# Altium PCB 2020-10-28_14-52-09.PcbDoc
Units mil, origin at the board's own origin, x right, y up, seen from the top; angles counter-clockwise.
Board outline 2200 x 1600 mil, 4 copper layers (Top Layer, MidLayer1, MidLayer2, Bottom Layer); 14 components, 6 nets, 34 pads, 44 vias.
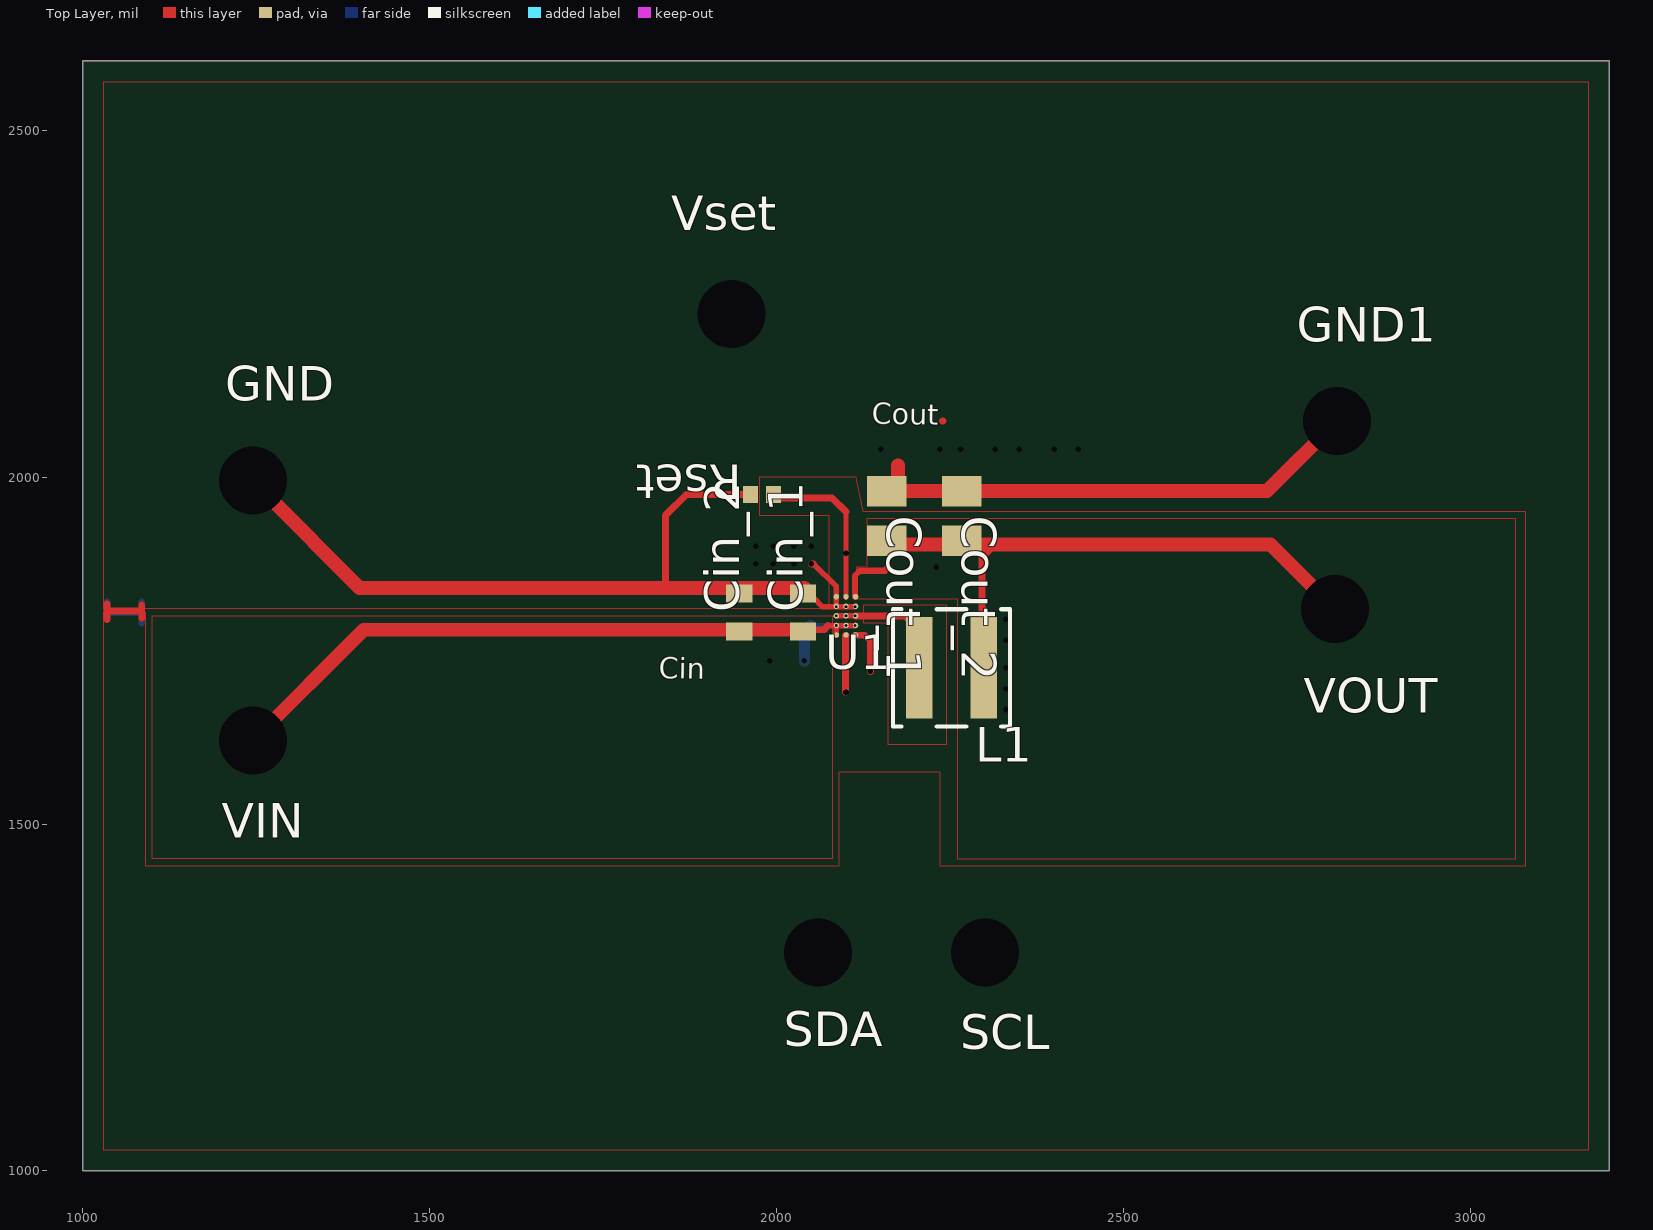
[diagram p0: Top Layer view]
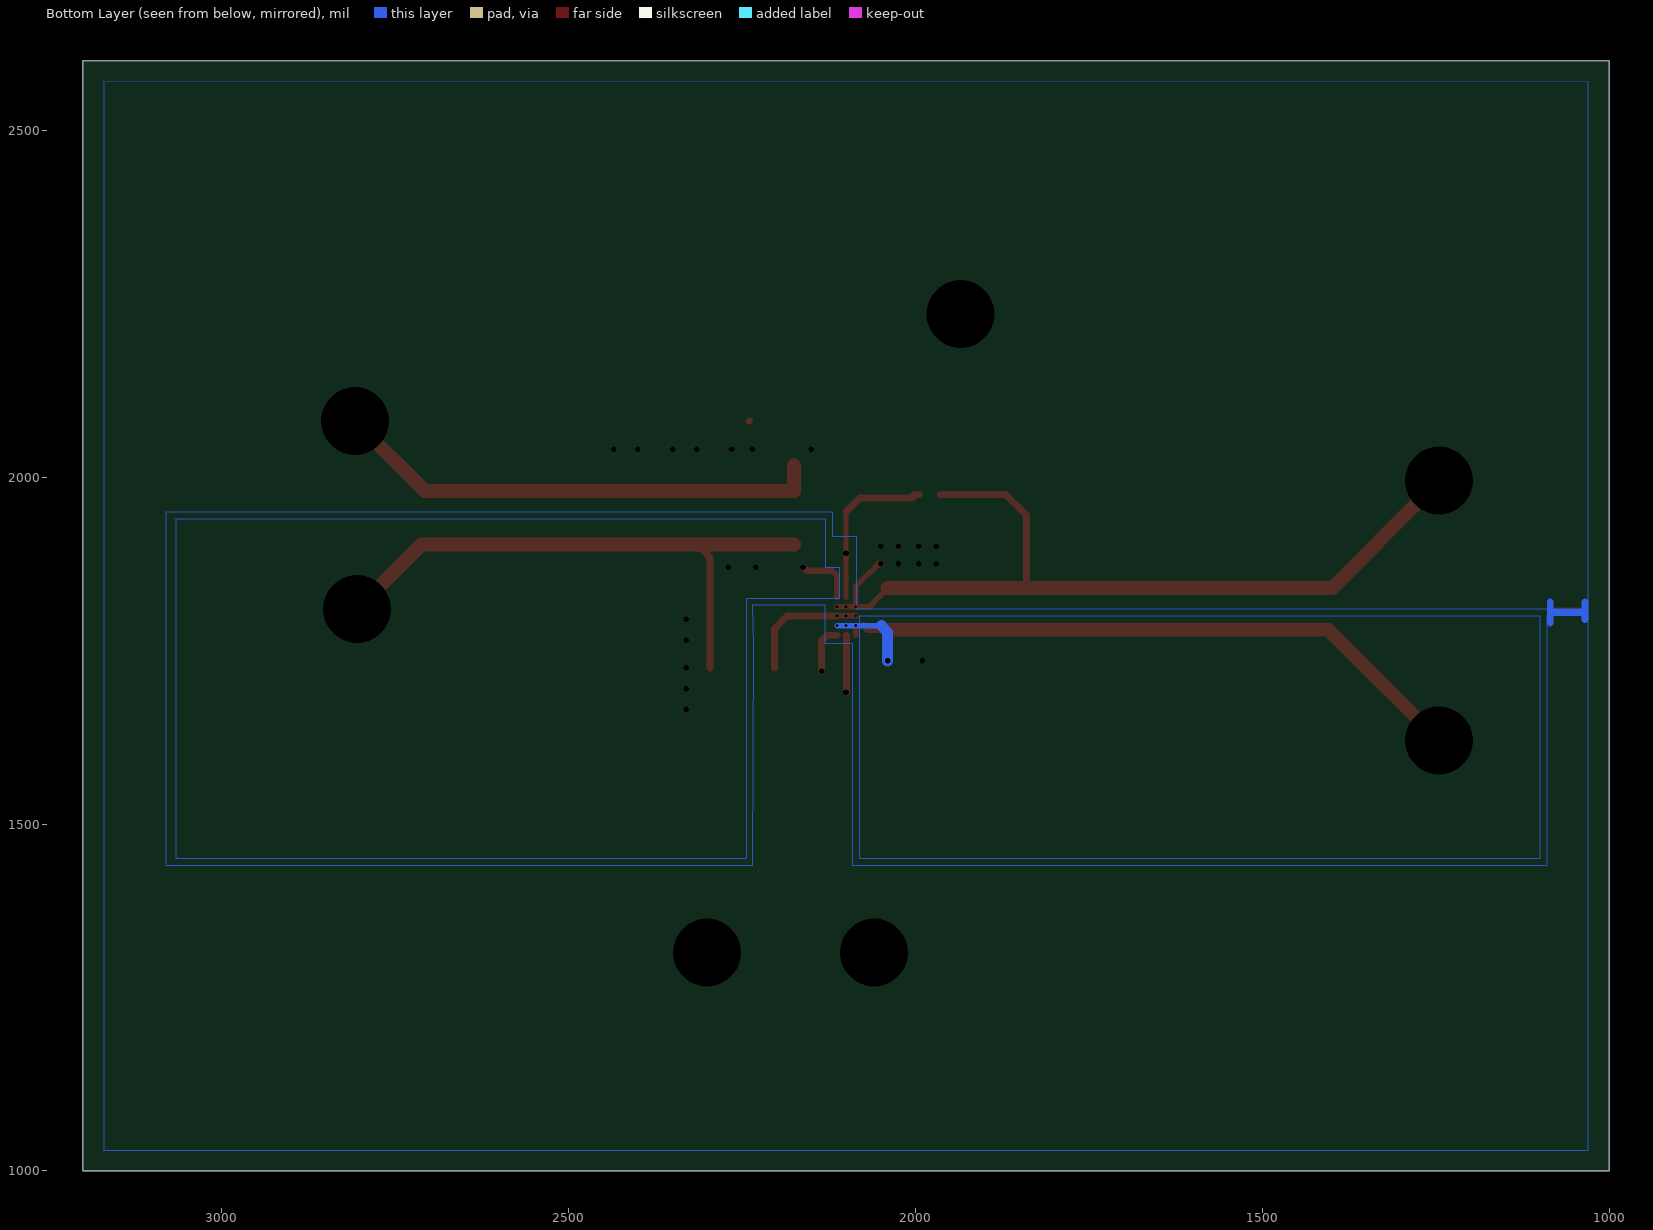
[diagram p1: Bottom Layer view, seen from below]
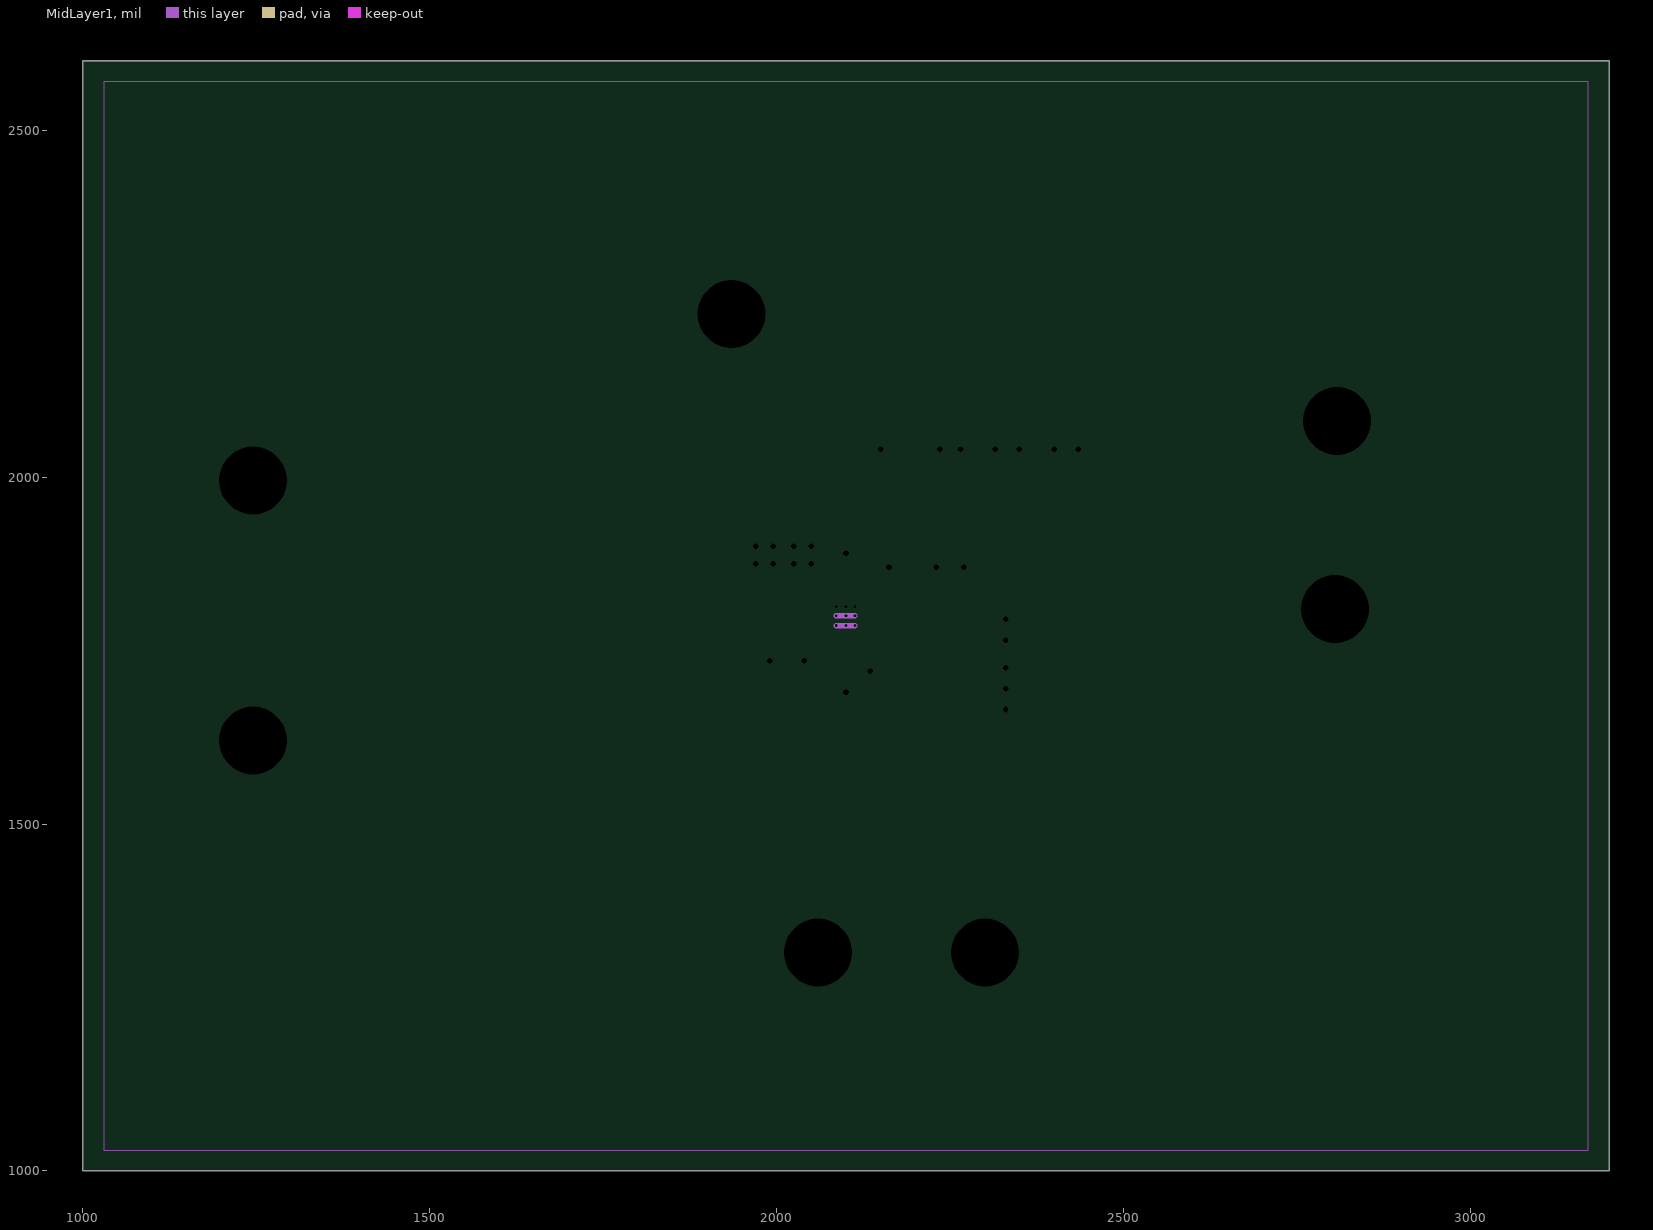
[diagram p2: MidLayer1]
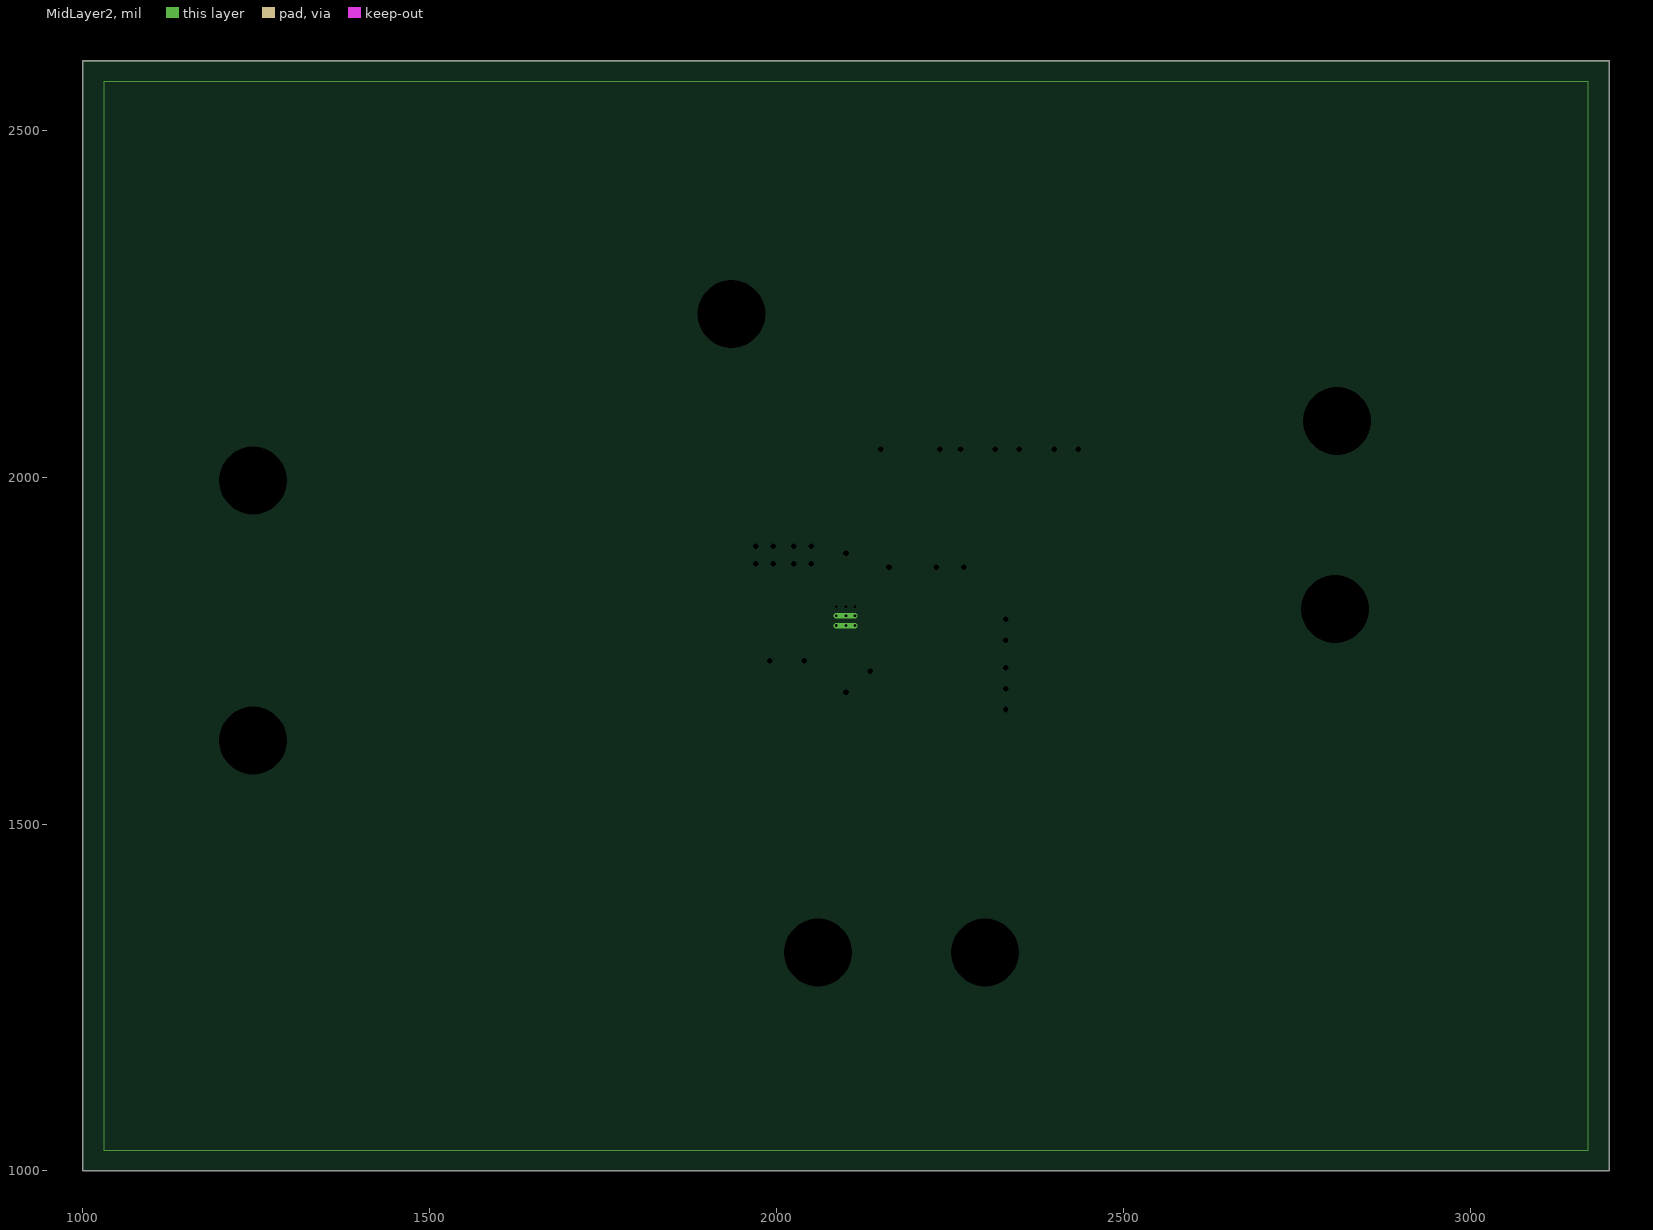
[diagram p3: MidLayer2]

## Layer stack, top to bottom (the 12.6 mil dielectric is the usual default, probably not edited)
Top Layer: signal copper 1.4
Dielectric: core 12.6, FR-4, Dk 4.8
MidLayer1: signal copper 1.4
Dielectric: prepreg 12.6, FR-4, Dk 4.8
MidLayer2: signal copper 1.4
Dielectric: core 12.6, FR-4, Dk 4.8
Bottom Layer: signal copper 1.4

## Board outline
1000,1000 3200,1000 3200,2600 1000,2600

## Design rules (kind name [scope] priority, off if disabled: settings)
PlaneConnect [All] p0: scope1count=1 scope1_0_kind=Board scope1_0_value=Board scope2count=1 scope2_0_kind=Board scope2_0_value=Board commentlength=0 planeconnectstyle=Direct reliefexpansion=20 reliefentries=4 reliefconductorwidth=10 reliefairgap=10
PlaneConnect [All] p1: planeconnectstyle=Direct reliefexpansion=20 reliefentries=4 reliefconductorwidth=10 reliefairgap=10
PolygonConnect [All] p0: scope1count=1 scope1_0_kind=Board scope1_0_value=Board scope2count=1 scope2_0_kind=Board scope2_0_value=Board commentlength=0 connectstyle=Direct reliefconductorwidth=10 reliefentries=4 polygonreliefangle="90 Angle"
PolygonConnect [All] p1: connectstyle=Direct reliefconductorwidth=10 reliefentries=4 polygonreliefangle="90 Angle"

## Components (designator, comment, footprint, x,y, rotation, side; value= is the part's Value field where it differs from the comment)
Cin_1 "" 0603 2038,1805 r90 top
Cin_2 "" 0603 1946,1805 r90 top
Cout_1 "" 0805 2159,1944 r270 top
Cout_2 "" 0805 2267,1944 r270 top
GND "" TP-1502 1244,1994 r0 top
GND1 "" TP-1502 2807,2081 r0 top
L1 "" XAL4020 2252,1725 r0 top
Rset "" 0402 1979,1975 r180 top
SCL "" TP-1502 2300,1314 r0 top
SDA "" TP-1502 2059,1314 r0 top
U1 "" YCG0015ACAC 2100,1800 r0 top
VIN "" TP-1502 1244,1620 r0 top
VOUT "" TP-1502 2805,1809 r0 top
Vset "" TP-1502 1935,2235 r0 top

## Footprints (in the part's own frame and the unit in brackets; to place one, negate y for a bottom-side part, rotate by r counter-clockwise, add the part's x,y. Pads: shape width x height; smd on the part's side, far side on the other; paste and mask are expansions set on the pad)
0402 [mil]
  rect 22x24 smd: 1(-16.5,0) 2(16.5,0)
0603 [mil]
  rect 26x38 smd: 1(-27.5,0) 2(27.5,0)
0805 [mil]
  rect 44x57 smd: 1(-35.5,0) 2(35.5,0)
TP-1502 [mil]
  round 65 / inner round 0 / far side round 65 hole 32: 1(0,0)
XAL4020 [mil]
  rect 38x146 smd: 1(-46.5,0) 2(46.5,0)
  silkscreen extent -84,-84 84,84
YCG0015ACAC [mm]
  round 0.2 smd: 1(-0.35,0.7) 2(0,0.7) 3(0.35,0.7) 4(-0.35,0.35) 5(0,0.35) 6(0.35,0.35) 7(-0.35,0) 8(0,0) 9(0.35,0) 10(-0.35,-0.35) 11(0,-0.35) 12(0.35,-0.35) 13(-0.35,-0.7) 14(0,-0.7) 15(0.35,-0.7)

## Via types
v1: diameter 0, hole 8, Top Layer to Bottom Layer, 28 vias
v2: diameter 0, hole 4, Top Layer to Bottom Layer, 9 vias
v3: diameter 0, hole 98, Top Layer to Bottom Layer, 7 vias

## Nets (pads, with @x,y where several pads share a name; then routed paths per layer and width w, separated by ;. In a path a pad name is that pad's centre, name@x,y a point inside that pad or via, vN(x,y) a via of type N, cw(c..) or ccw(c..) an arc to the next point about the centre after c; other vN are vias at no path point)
0: Cin_1.2 Cin_2.2 Cout_1.1 Cout_2.1 GND1.1 GND.1 Rset.1 Rset.2 U1.1 U1.2 U1.4 U1.5 U1.6 Vset.1 | length 2912
  Top Layer w7.8: Cin_1.2@2040,1840 2066,1813 v2(2086,1813) v2(2100,1813) v2(2113,1813) ; U1.1@2086,1827 2086,1842 ; U1.2@2100,1827 v1(2100,1890) 2100,1950
  Top Layer w8: 2053,1875 2086,1842 ; v2(2086,1813) U1.1@2086,1827
  Top Layer w10: 1035,1795 1035,1807 ; 1035,1817 1035,1807 ; 1085,1797 1085,1807 ; 1085,1816 1085,1807 ; 1840,1840 1840,1945 1870,1975 Rset.2@1960,1975 ; v3(1935,2235) Vset.1@1940,2240 ; Rset.2@1955,1974.5 Rset.2@1964,1974.5 ; Rset.1@1994,1974.5 Rset.1@2003,1974.5 ; Rset.1@1999,1975 2004,1970 2080,1970 2100,1950 ; v1(2050,1875) 2053,1875 ; 2239,2081 2240,2081 ; 1035,1807 1085,1807
  Top Layer w20: v3(1245,1995) 1265,1975 1399,1840 1840,1840 Cin_1.2@2040,1840 ; 2175,2017 2175,1980 2707,1980 v3(2808,2081)
  Mid-Layer 4 w10: v3(1935,2235) 2055,2235 2100,2190 v1(2100,1890)
  Bottom Layer w10: 1035,1795 1035,1805 ; 1035,1820 1035,1805 ; 1085,1790 1085,1805 ; 1085,1820 1085,1805 ; 1035,1805 1085,1805
  other v1: 1970,1875 1995,1875 2025,1875 1970,1900 1995,1900 2025,1900 2050,1900 2150,2040 2235,2040 2265,2040 2315,2040 2350,2040 2400,2040 2435,2040
4: Cin_1.1 Cin_2.1 U1.10 U1.11 U1.12 U1.13 VIN.1 | length 1177.2
  Top Layer w7.8: 2074,1786 v2(2086,1786) ; U1.13@2086,1772 v2(2086,1786) ; v2(2113,1786) v2(2100,1786) v2(2086,1786)
  Top Layer w10: Cin_1.1@2040,1780 2068,1780 2074,1786
  Top Layer w20: v3(1245,1620) 1405,1780 Cin_1.1@2040,1780
  MidLayer1 w7.8: v2(2086,1786) v2(2100,1786) v2(2113,1786)
  MidLayer2 w7.8: v2(2086,1786) v2(2100,1786) v2(2113,1786)
  Mid-Layer 3 w7.8: v2(2086,1786) v2(2100,1786) v2(2113,1786)
  Mid-Layer 4 w7.8: v2(2086,1786) v2(2100,1786) v2(2113,1786)
  Bottom Layer w7.8: 2049,1786 v2(2086,1786) v2(2100,1786) v2(2113,1786)
  Bottom Layer w15.7: v1(2040,1735) 2040,1776 2049,1786
  other v1: 1990,1735
7: Cout_1.2 Cout_2.2 L1.2 U1.3 VOUT.1 | length 1014.5
  Top Layer w8: U1.3@2113,1827 2113,1858 2120,1865
  Top Layer w10: 2120,1865 2156,1865 v1(2162,1870) ; L1.2@2296,1725 2296,1884 2315,1903
  Top Layer w20: Cout_1.2@2175,1903 2315,1903 2712,1903 v3(2805,1810)
  Mid-Layer 4 w7.8: v1(2230,1870) v1(2270,1870) 2304,1870 2305,1869
  other v1: 2330,1665 2330,1695 2330,1725 2330,1765 2330,1795
13: SCL.1 U1.15 | length 543
  Top Layer w10: U1.15@2113,1772 2127,1772 2135,1765 v1(2135,1720)
  Mid-Layer 4 w10: v1(2135,1720) 2135,1550 2300,1385 v3(2300,1315)
14: SDA.1 U1.14 | length 474.6
  Top Layer w10: 2099,1690 2099,1772 U1.14@2100,1772
  Mid-Layer 4 w10: v3(2060,1315) 2060,1510 2100,1550 v1(2100,1690)
15: L1.1 U1.7 U1.8 U1.9 | length 289.2
  Top Layer w7.8: v2(2086,1800) v2(2100,1800) v2(2113,1800)
  Top Layer w10: v2(2113,1800) 2185,1800 2203,1781 L1.1@2203,1725
  MidLayer1 w7.8: v2(2086,1800) v2(2100,1800) v2(2113,1800)
  MidLayer2 w7.8: v2(2086,1800) v2(2100,1800) v2(2113,1800)
  Mid-Layer 3 w7.8: v2(2086,1800) v2(2100,1800) v2(2113,1800)
  Mid-Layer 4 w7.8: v2(2086,1800) v2(2100,1800) v2(2113,1800)

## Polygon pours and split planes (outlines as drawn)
4 on Top Layer " " (solid, pour order 2): 2080,1800 2080,1450 1100,1450 1100,1800
15 on Top Layer " " (solid, pour order 3): 2245,1815 2125,1815 2125,1790 2160,1790 2160,1615 2245,1615
7 on Top Layer " " (solid, pour order 4): 2130,1870 2115,1870 2115,1825 2260,1825 2260,1450 3065,1450 3065,1940 2130,1940
0 on Top Layer " " (solid, pour order 10): 1975,2000 1975,1945 2075,1945 2075,1810 1030,1810 1030,2570 3170,2570 3170,1030 1030,1030 1030,1805 1090,1805 1090,1440 2090,1440 2090,1575 2235,1575 2235,1440 3080,1440 3080,1950 2225,1950 2125,1950 2115,2000
7 on Bottom Layer " " (solid, pour order 0): 2130,1870 2110,1870 2110,1825 2244,1825 2244,1450 3065,1450 3065,1940 2680,1940 2130,1940
4 on Bottom Layer " " (solid, pour order 1): 1100,1800 1100,1450 2080,1450 2080,1800
0 on Bottom Layer " " (solid, pour order 9): 2130,1760 2130,1815 2235,1815 2234,1760 2235,1440 3080,1440 3080,1950 2120,1950 2120,1915 2085,1915 2085,1810 1030,1810 1030,2569 3170,2570 3170,1030 1030,1030 1030,1800 1090,1800 1090,1440 2090,1440 2090,1760
0 on Mid-Layer 4 " " (solid, pour order 5): 1030,2570 3170,2570 3169,1030 1029,1030
0 on Mid-Layer 3 " " (solid, pour order 6): 1030,2570 3170,2570 3170,1030 1029,1030
0 on MidLayer2 " " (solid, pour order 7): 1030,1030 3170,1030 3170,2570 1030,2570
0 on MidLayer1 " " (solid, pour order 8): 1030,1030 3170,1030 3170,2570 1030,2570
no net on Top Paste "Top Layer-No Net" (solid, remove dead copper): 2095.87,1811.61 2095.87,1815.94 2097.83,1817.91 2102.17,1817.91 2104.13,1815.94 2104.13,1811.61 2102.17,1809.65 2097.83,1809.65
no net on Top Paste "Top Layer-No Net" (solid, remove dead copper): 2082.09,1811.61 2082.09,1815.94 2084.06,1817.91 2088.39,1817.91 2090.35,1815.94 2090.35,1811.61 2088.39,1809.65 2084.06,1809.65
no net on Top Paste "Top Layer-No Net" (solid, remove dead copper): 2109.65,1825.39 2109.65,1829.72 2111.61,1831.69 2115.94,1831.69 2117.91,1829.72 2117.91,1825.39 2115.94,1823.43 2111.61,1823.43
no net on Top Paste "Top Layer-No Net" (solid, remove dead copper): 2095.87,1825.39 2095.87,1829.72 2097.83,1831.69 2102.17,1831.69 2104.13,1829.72 2104.13,1825.39 2102.17,1823.43 2097.83,1823.43
no net on Top Paste "Top Layer-No Net" (solid, remove dead copper): 2082.09,1825.39 2082.09,1829.72 2084.06,1831.69 2088.39,1831.69 2090.35,1829.72 2090.35,1825.39 2088.39,1823.43 2084.06,1823.43

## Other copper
Multi-Layer:
  the board outline again, w1

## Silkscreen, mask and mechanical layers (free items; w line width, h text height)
Top Overlay:
  text "Cout" at 2137,2077 h30 r359
  text "Cin" at 1830,1710 h30 r359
